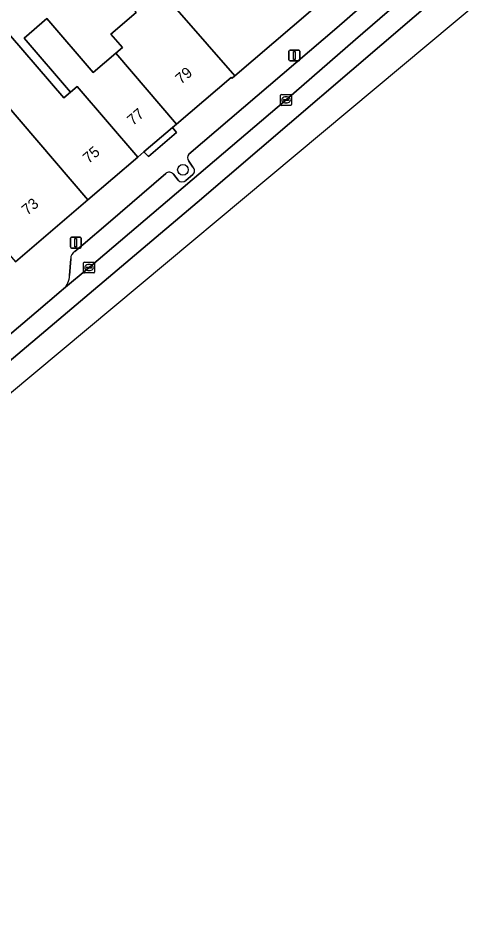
# Model space of a CAD drawing. Extents: x 161772 to 163126, y 383092 to 383917.
# Drawn here: x 162460.7 to 162503.5, y 383299.4 to 383382.9 of the extents above; entities that cross this region are included whole.
import ezdxf

# ---------------------------------------------------------------- set-up
doc = ezdxf.new("R2010")
doc.units = 0
for name, color, linetype in [('IMGEO_Boom', 7, 'Continuous'), ('IMGEO_Erf', 7, 'Continuous'), ('IMGEO_Groenvoorziening', 7, 'Continuous'), ('IMGEO_Kolk', 7, 'Continuous'), ('IMGEO_Lichtmast', 7, 'Continuous'), ('IMGEO_Pand', 7, 'Continuous'), ('IMGEO_Pand_nummerreeks', 7, 'Continuous'), ('IMGEO_Parkeervlak_open', 7, 'Continuous'), ('IMGEO_Rijbaan_lokaal_gesloten', 7, 'Continuous'), ('IMGEO_Voetpad_open', 7, 'Continuous')]:
    doc.layers.add(name, color=color, linetype=linetype)

msp = doc.modelspace()

# ---------------------------------------------------------------- linework, layer by layer
at = {"layer": 'IMGEO_Boom'}
msp.add_circle((162475.809, 383368.975), 0.489, dxfattribs=at)
at = {"layer": 'IMGEO_Erf'}
msp.add_lwpolyline([(162458.596, 383382.858), (162464.839, 383375.593), (162465.468, 383376.133), (162461.196, 383381.104), (162463.287, 383382.901), (162467.559, 383377.93), (162469.634, 383379.712), (162470.244, 383380.236), (162469.181, 383381.473), (162471.492, 383383.46)], dxfattribs=at)
at = {"layer": 'IMGEO_Groenvoorziening'}
msp.add_lwpolyline([(162475.227, 383372.405), (162474.842, 383372.866), (162472.224, 383370.627), (162472.633, 383370.198)], close=True, dxfattribs=at)
at = {"layer": 'IMGEO_Kolk'}
for p, q in [((162484.79, 383374.987), (162484.79, 383375.839)), ((162484.865, 383375.913), (162485.717, 383375.913)), ((162485.791, 383375.839), (162485.791, 383374.987)), ((162485.049, 383375.407), (162485.049, 383375.419)), ((162485.487, 383375.37), (162485.089, 383375.37)), ((162485.092, 383375.456), (162485.49, 383375.456)), ((162485.301, 383375.133), (162485.276, 383375.133)), ((162485.278, 383375.693), (162485.303, 383375.693)), ((162485.533, 383375.419), (162485.533, 383375.407)), ((162485.717, 383374.913), (162484.865, 383374.913)), ((162466.67, 383359.561), (162466.67, 383360.413)), ((162466.745, 383360.487), (162467.597, 383360.487)), ((162466.929, 383359.981), (162466.929, 383359.993)), ((162467.367, 383359.944), (162466.969, 383359.944)), ((162466.972, 383360.03), (162467.37, 383360.03)), ((162467.158, 383360.267), (162467.183, 383360.267)), ((162467.413, 383359.993), (162467.413, 383359.981)), ((162467.671, 383360.413), (162467.671, 383359.561)), ((162467.597, 383359.487), (162466.745, 383359.487)), ((162467.181, 383359.707), (162467.156, 383359.707))]:
    msp.add_line(p, q, dxfattribs=at)
for points in [[(162484.79, 383374.987), (162484.79, 383375.839)], [(162484.865, 383375.913), (162485.717, 383375.913)], [(162485.791, 383375.839), (162485.791, 383374.987)], [(162485.717, 383374.913), (162484.865, 383374.913)], [(162466.67, 383359.561), (162466.67, 383360.413)], [(162466.745, 383360.487), (162467.597, 383360.487)], [(162467.671, 383360.413), (162467.671, 383359.561)], [(162467.597, 383359.487), (162466.745, 383359.487)]]:
    msp.add_lwpolyline(points, dxfattribs=at)
for centre, radius, start, end in [((162484.867, 383375.837), 0.0765, 91.55205, 178.44795), ((162484.867, 383375.837), 0.0765, 91.55205, 178.44795), ((162485.715, 383375.837), 0.0765, 1.55205, 88.44795), ((162485.715, 383375.837), 0.0765, 1.55205, 88.44795), ((162484.867, 383374.989), 0.0765, 181.55205, 268.44795), ((162484.867, 383374.989), 0.0765, 181.55205, 268.44795), ((162485.089, 383375.416), 0.0403, 85.87752, 175.75265), ((162485.086, 383375.406), 0.0366, 178.93798, 274.71019), ((162485.49, 383375.413), 0.043, 264.86636, 352.45326), ((162485.494, 383375.418), 0.0386, 1.73085, 96.63898), ((162485.715, 383374.989), 0.0765, 271.55205, 358.44795), ((162485.715, 383374.989), 0.0765, 271.55205, 358.44795), ((162466.747, 383360.411), 0.0765, 91.55205, 178.44795), ((162466.747, 383360.411), 0.0765, 91.55205, 178.44795), ((162466.969, 383359.99), 0.0403, 85.87752, 175.75265), ((162466.966, 383359.98), 0.0366, 178.93798, 274.71019), ((162467.37, 383359.987), 0.043, 264.86636, 352.45326), ((162467.374, 383359.992), 0.0386, 1.73085, 96.63898), ((162467.595, 383360.411), 0.0765, 1.55205, 88.44795), ((162467.595, 383360.411), 0.0765, 1.55205, 88.44795), ((162466.747, 383359.563), 0.0765, 181.55205, 268.44795), ((162466.747, 383359.563), 0.0765, 181.55205, 268.44795), ((162467.595, 383359.563), 0.0765, 271.55205, 358.44795), ((162467.595, 383359.563), 0.0765, 271.55205, 358.44795)]:
    msp.add_arc(centre, radius, start, end, dxfattribs=at)
for centre, major_axis, ratio, start_param, end_param in [((162485.277, 383375.413), (-0.387, 0.002), 0.722429, 4.712389, 7.853982), ((162485.302, 383375.413), (-0.39, 0.002), 0.717154, 1.570796, 4.712389), ((162467.157, 383359.987), (-0.387, 0.002), 0.722429, 4.712389, 7.853982), ((162467.182, 383359.987), (-0.39, 0.002), 0.717154, 1.570796, 4.712389)]:
    msp.add_ellipse(centre, major_axis=major_axis, ratio=ratio, start_param=start_param, end_param=end_param, dxfattribs=at)
at = {"layer": 'IMGEO_Lichtmast'}
for p, q in [((162485.661, 383380), (162486.451, 383380)), ((162486.451, 383380), (162485.661, 383380)), ((162485.561, 383379.1), (162485.561, 383379.9)), ((162485.561, 383379.9), (162485.561, 383379.1)), ((162486.551, 383379.9), (162486.551, 383379.1)), ((162486.551, 383379.1), (162486.551, 383379.9)), ((162486.451, 383379), (162485.661, 383379)), ((162485.661, 383379), (162486.451, 383379)), ((162465.452, 383361.878), (162465.452, 383362.678)), ((162465.452, 383362.678), (162465.452, 383361.878)), ((162465.552, 383362.778), (162466.342, 383362.778)), ((162466.342, 383362.778), (162465.552, 383362.778)), ((162466.442, 383362.678), (162466.442, 383361.878)), ((162466.442, 383361.878), (162466.442, 383362.678)), ((162466.342, 383361.778), (162465.552, 383361.778)), ((162465.552, 383361.778), (162466.342, 383361.778))]:
    msp.add_line(p, q, dxfattribs=at)
for points in [[(162485.981, 383379.875), (162486.131, 383379.875), (162486.131, 383379.125), (162485.981, 383379.125), (162485.981, 383379.875)], [(162465.872, 383362.653), (162466.022, 383362.653), (162466.022, 383361.903), (162465.872, 383361.903), (162465.872, 383362.653)]]:
    msp.add_lwpolyline(points, dxfattribs=at)
for centre, start, end in [((162485.661, 383379.9), 90, 180), ((162485.661, 383379.9), 90, 180), ((162486.451, 383379.9), 0, 90), ((162486.451, 383379.9), 360, 90), ((162485.661, 383379.1), 180, 270), ((162485.661, 383379.1), 180, 270), ((162486.451, 383379.1), 270, 0), ((162486.451, 383379.1), 270, 0), ((162465.552, 383362.678), 90, 180), ((162465.552, 383362.678), 90, 180), ((162466.342, 383362.678), 0, 90), ((162466.342, 383362.678), 360, 90), ((162465.552, 383361.878), 180, 270), ((162465.552, 383361.878), 180, 270), ((162466.342, 383361.878), 270, 0), ((162466.342, 383361.878), 270, 0)]:
    msp.add_arc(centre, 0.1, start, end, dxfattribs=at)
at = {"layer": 'IMGEO_Pand'}
for points in [[(162500, 383394.271), (162503.481, 383397.254), (162500, 383401.316), (162493.01, 383409.473), (162489.4, 383406.371), (162474.314, 383393.573), (162478.415, 383388.739), (162474.088, 383385.068), (162474.161, 383384.983), (162475.491, 383383.445), (162480.594, 383377.64)], [(162474.088, 383385.068), (162470.086, 383389.699), (162467.811, 383387.744), (162471.492, 383383.46), (162469.181, 383381.473), (162470.244, 383380.236), (162469.634, 383379.712), (162475.226, 383373.195), (162480.244, 383377.488), (162480.348, 383377.43), (162480.594, 383377.64), (162475.491, 383383.445), (162474.161, 383384.983)], [(162466.072, 383376.652), (162465.468, 383376.133), (162464.839, 383375.593), (162458.596, 383382.858), (162452.564, 383377.675), (162455.713, 383375.167), (162457.829, 383376.985), (162467.068, 383366.216), (162471.656, 383370.141)], [(162469.634, 383379.712), (162467.559, 383377.93), (162463.287, 383382.901), (162461.196, 383381.104), (162465.468, 383376.133), (162466.072, 383376.652), (162471.656, 383370.141), (162472.224, 383370.627), (162474.842, 383372.866), (162475.226, 383373.195)], [(162457.829, 383376.985), (162455.713, 383375.167), (162455.406, 383374.903), (162458.646, 383371.132), (162457.696, 383370.315), (162456.935, 383371.201), (162453.673, 383368.398), (162454.048, 383367.895), (162460.4, 383360.511), (162467.068, 383366.216)]]:
    msp.add_lwpolyline(points, close=True, dxfattribs=at)
at = {"layer": 'IMGEO_Parkeervlak_open'}
for points in [[(162497.356, 383388.716), (162495.209, 383386.638), (162489.959, 383382.059), (162476.359, 383370.433)], [(162464.826, 383358.018), (162467.172, 383359.987), (162485.292, 383375.412), (162491.686, 383380.972), (162495.478, 383384.248), (162499.449, 383387.988)], [(162476.361, 383369.769), (162476.723, 383369.221)], [(162474.223, 383368.628), (162468.918, 383364.081), (162466.617, 383362.121), (162465.859, 383361.474)], [(162475.373, 383368.031), (162474.929, 383368.57)], [(162476.72, 383368.535), (162476.08, 383367.985)], [(162465.488, 383360.803), (162465.368, 383359.246)]]:
    msp.add_lwpolyline(points, dxfattribs=at)
for centre, radius, start, end in [((162476.727, 383370.102), 0.495, 138.00537, 222.33978), ((162476.43, 383368.879), 0.45, 310.1458, 49.35307), ((162474.549, 383368.275), 0.481, 37.88566, 132.72139), ((162475.751, 383368.388), 0.52, 223.33845, 309.2163), ((162466.221, 383360.836), 0.734, 119.56619, 182.55686), ((162463.691, 383359.253), 1.677, 312.60002, 359.76972)]:
    msp.add_arc(centre, radius, start, end, dxfattribs=at)
at = {"layer": 'IMGEO_Rijbaan_lokaal_gesloten'}
for points in [[(162174.82, 383097.237), (162181.627, 383109.075), (162185.082, 383115.085), (162267.807, 383184.457), (162331.864, 383238.174), (162334.992, 383240.797), (162372.302, 383272.085), (162439.186, 383331.12), (162452.553, 383342.284), (162503.092, 383384.494), (162503.092, 383384.494), (162502.922, 383384.713), (162501.18, 383386.596), (162499.827, 383385.459), (162477.128, 383365.985), (162459.036, 383350.651), (162175.227, 383109.464), (162171.607, 383105.25), (162169.364, 383100.909), (162168.706, 383099.067), (162168.602, 383098.586), (162174.82, 383097.237), (162174.82, 383097.237)], [(162459.036, 383350.651), (162477.128, 383365.985), (162499.827, 383385.459)], [(162495.478, 383384.248), (162491.686, 383380.972), (162485.292, 383375.412), (162467.172, 383359.987), (162464.826, 383358.018), (162464.617, 383357.843), (162462.318, 383355.895), (162459.448, 383353.446), (162457.797, 383352.048), (162457.074, 383351.433), (162447.031, 383342.754), (162439.171, 383335.995), (162431.011, 383328.965), (162424.727, 383323.567), (162416.702, 383316.671)]]:
    msp.add_lwpolyline(points, dxfattribs=at)
at = {"layer": 'IMGEO_Voetpad_open'}
for points in [[(162500, 383394.271), (162480.594, 383377.64), (162480.348, 383377.43), (162480.244, 383377.488), (162475.226, 383373.195), (162474.842, 383372.866), (162475.227, 383372.405), (162472.633, 383370.198), (162472.224, 383370.627), (162471.656, 383370.141), (162467.068, 383366.216), (162460.4, 383360.511)], [(162476.359, 383370.433), (162489.959, 383382.059), (162495.209, 383386.638), (162497.356, 383388.716)], [(162476.723, 383369.221), (162476.361, 383369.769)], [(162465.859, 383361.474), (162466.617, 383362.121), (162468.918, 383364.081), (162474.223, 383368.628)], [(162474.929, 383368.57), (162475.373, 383368.031)], [(162476.08, 383367.985), (162476.72, 383368.535)], [(162465.368, 383359.246), (162465.488, 383360.803)], [(162457.074, 383351.433), (162457.797, 383352.048), (162459.448, 383353.446), (162462.318, 383355.895), (162464.617, 383357.843), (162464.826, 383358.018)]]:
    msp.add_lwpolyline(points, dxfattribs=at)
for centre, radius, start, end in [((162476.727, 383370.102), 0.495, 138.00537, 222.33978), ((162476.43, 383368.879), 0.45, 310.1458, 49.35307), ((162474.549, 383368.275), 0.481, 37.88566, 132.72139), ((162475.751, 383368.388), 0.52, 223.33845, 309.2163), ((162466.221, 383360.836), 0.734, 119.56619, 182.55686), ((162463.691, 383359.253), 1.677, 312.60002, 359.76972)]:
    msp.add_arc(centre, radius, start, end, dxfattribs=at)

# ---------------------------------------------------------------- texts
at = {"layer": 'IMGEO_Pand_nummerreeks'}
for s, rotation, p in [('79', 40.61125, (162475.633, 383376.802)), ('77', 40.61698, (162471.205, 383373.005)), ('75', 40.61698, (162467.13, 383369.511)), ('73', 40.00391, (162461.492, 383364.75))]:
    msp.add_text(s, height=1, rotation=rotation, dxfattribs=at).set_placement(p)

doc.saveas('drawing.dxf')
